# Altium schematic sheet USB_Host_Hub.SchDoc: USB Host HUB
size A3; Project: STM32MP15-DISCO PI; Date: Not used; ApprovedBy: Not used; CheckedBy: Not used; Author: Not used; CompanyName: STMicroelectronics; DrawnBy: Not used; Engineer: Not used; Organization: Not used; Address1: Not used; Address2: Not used; Address3: Not used; Address4: Not used; DocumentNumber: 12; Revision: Not used; SheetNumber: 12; SheetTotal: 17
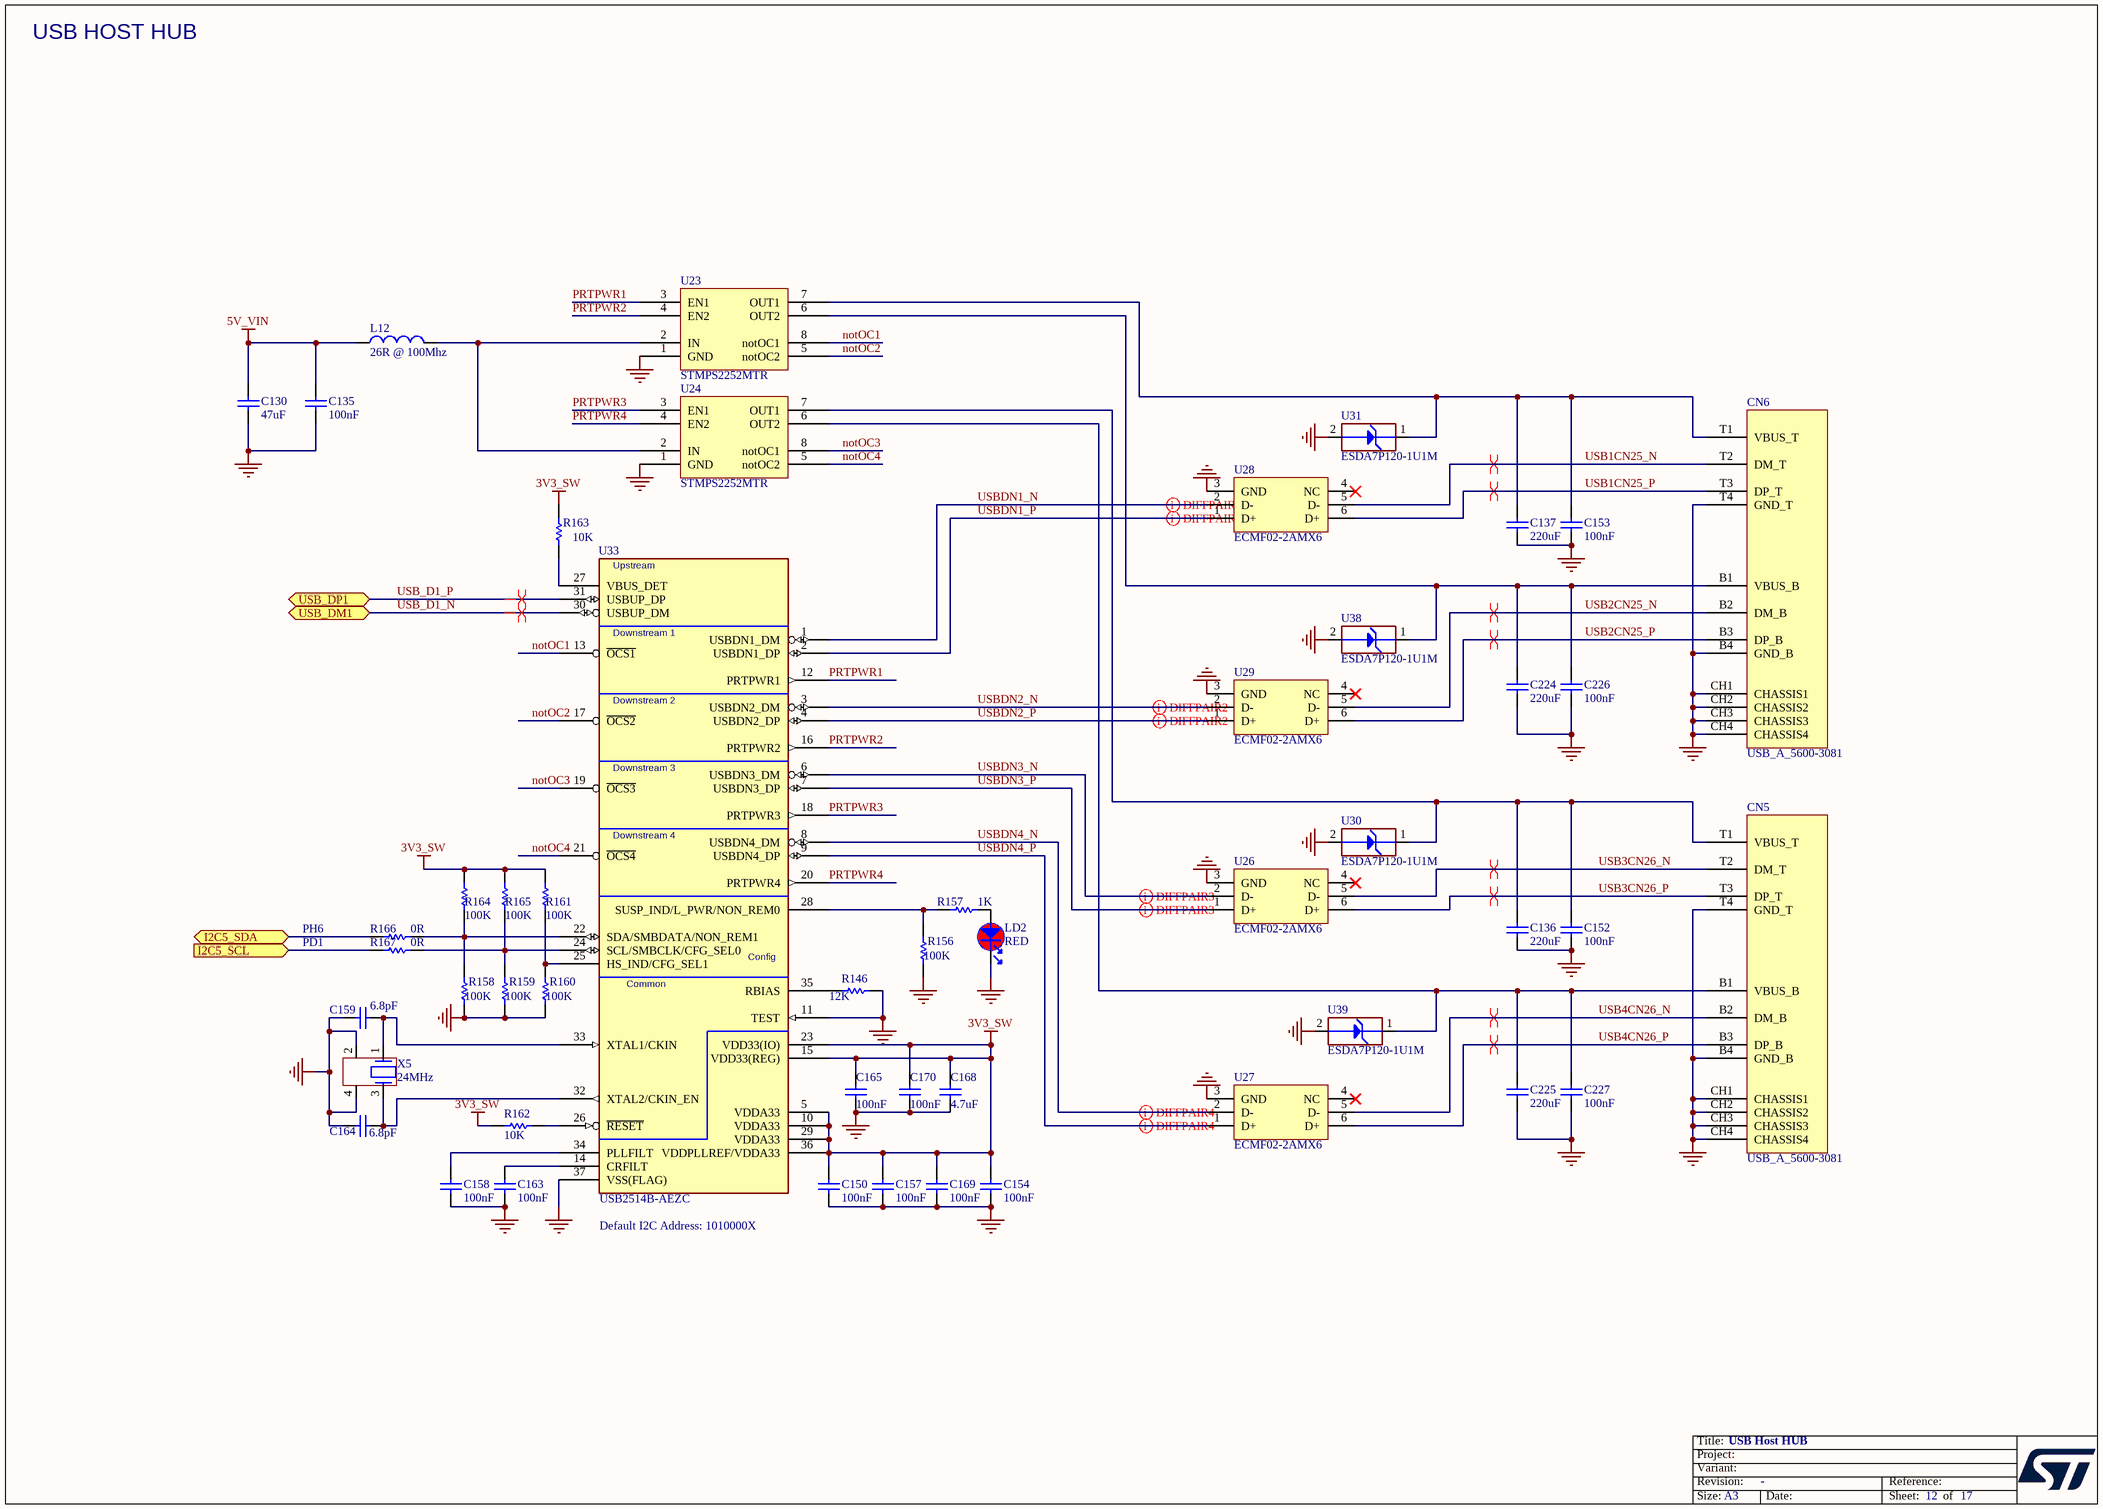
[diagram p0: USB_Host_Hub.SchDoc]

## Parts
C130  value 47uF  [C1206_H1P6]  (hidden comment: Capacitor)
C135  value 100nF  [C0402]  (hidden comment: Capacitor)
C136  value 220uF  [C1206_H1P6]  (hidden comment: Capacitor)
C137  value 220uF  [C1206_H1P6]  (hidden comment: Capacitor)
C150  value 100nF  [C0402]  (hidden comment: Capacitor)
C152  value 100nF  [C0402]  (hidden comment: Capacitor)
C153  value 100nF  [C0402]  (hidden comment: Capacitor)
C154  value 100nF  [C0402]  (hidden comment: Capacitor)
C157  value 100nF  [C0402]  (hidden comment: Capacitor)
C158  value 100nF  [C0402]  (hidden comment: Capacitor)
C159  value 6.8pF  [C0402]  (hidden comment: Capacitor)
C163  value 100nF  [C0402]  (hidden comment: Capacitor)
C164  value 6.8pF  [C0402]  (hidden comment: Capacitor)
C165  value 100nF  [C0402]  (hidden comment: Capacitor)
C168  value 4.7uF  [C0402]  (hidden comment: Capacitor)
C169  value 100nF  [C0402]  (hidden comment: Capacitor)
C170  value 100nF  [C0402]  (hidden comment: Capacitor)
C224  value 220uF  [C1206_H1P6]  (hidden comment: Capacitor)
C225  value 220uF  [C1206_H1P6]  (hidden comment: Capacitor)
C226  value 100nF  [C0402]  (hidden comment: Capacitor)
C227  value 100nF  [C0402]  (hidden comment: Capacitor)
CN5  value USB_A_5600-3081  [CON_DUAL-USB-TYPE-A_CONEXCON_5600-3081]  (hidden comment: USB_DUAL_TYPEA_5600-3081)
CN6  value USB_A_5600-3081  [CON_DUAL-USB-TYPE-A_CONEXCON_5600-3081]  (hidden comment: USB_DUAL_TYPEA_5600-3081)
L12  value 26R @ 100Mhz  [FIL_0603_H0P65]  (hidden comment: BEAD)
LD2  value RED  [LED_0603_RED]  (hidden comment: LED_red)
R146  value 12K  [R0402]  (hidden comment: Resistor)
R156  value 100K  [R0402]  (hidden comment: Resistor)
R157  value 1K  [R0402]  (hidden comment: Resistor)
R158  value 100K  [R0402]  (hidden comment: Resistor)
R159  value 100K  [R0402]  (hidden comment: Resistor)
R160  value 100K  [R0402]  (hidden comment: Resistor)
R161  value 100K  [R0402]  (hidden comment: Resistor)
R162  value 10K  [R0402]  (hidden comment: Resistor)
R163  value 10K  [R0402]  (hidden comment: Resistor)
R164  value 100K  [R0402]  (hidden comment: Resistor)
R165  value 100K  [R0402]  (hidden comment: Resistor)
R166  value 0R  [R0402]  (hidden comment: Resistor)
R167  value 0R  [R0402]  (hidden comment: Resistor)
U23  STMPS2252MTR  [ICC_SO8_5X4_P127]
U24  STMPS2252MTR  [ICC_SO8_5X4_P127]
U26  ECMF02-2AMX6  [ESD_QFN-6L_1P7X1P5_P050]
U27  ECMF02-2AMX6  [ESD_QFN-6L_1P7X1P5_P050]
U28  ECMF02-2AMX6  [ESD_QFN-6L_1P7X1P5_P050]
U29  ECMF02-2AMX6  [ESD_QFN-6L_1P7X1P5_P050]
U30  value ESDA7P120-1U1M  [ESD_QFN1610_2N_1K_2A]  (hidden comment: ESD-TRANSIL)
U31  value ESDA7P120-1U1M  [ESD_QFN1610_2N_1K_2A]  (hidden comment: ESD-TRANSIL)
U33  USB2514B-AEZC  [ICC_QFN36-EPAD_6X6_P050]
U38  value ESDA7P120-1U1M  [ESD_QFN1610_2N_1K_2A]  (hidden comment: ESD-TRANSIL)
U39  value ESDA7P120-1U1M  [ESD_QFN1610_2N_1K_2A]  (hidden comment: ESD-TRANSIL)
X5  value 24MHz  [CRY_NX2016SA_4P]  (hidden comment: XTAL_4_PINS)

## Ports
I2C5_SCL (in), I2C5_SDA (bidir), USB_DM1 (bidir), USB_DP1 (bidir)

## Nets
3V3_SW: C150.2 C154.2 C157.2 C165.2 C168.2 C169.2 C170.2 R161.2 R162.1 R163.2 R164.2 R165.2 U33.5(VDDA33) U33.10(VDDA33) U33.15(VDD33(REG)) U33.23(VDD33(IO)) U33.29(VDDA33) U33.36(VDDPLLREF/VDDA33)
5V_VIN: C130.2 C135.2 L12.1
GND: C130.1 C135.1 C136.1 C137.1 C150.1 C152.1 C153.1 C154.1 C157.1 C158.1 C159.1 C163.1 C164.1 C165.1 C168.1 C169.1 C170.1 C224.1 C225.1 C226.1 C227.1 CN5.B4(GND_B) CN5.CH1(CHASSIS1) CN5.CH2(CHASSIS2) CN5.CH3(CHASSIS3) CN5.CH4(CHASSIS4) CN5.T4(GND_T) CN6.B4(GND_B) CN6.CH1(CHASSIS1) CN6.CH2(CHASSIS2) CN6.CH3(CHASSIS3) CN6.CH4(CHASSIS4) CN6.T4(GND_T) LD2.2 R146.1 R156.1 R158.1 R159.1 R160.1 U23.1(GND) U24.1(GND) U26.3(GND) U27.3(GND) U28.3(GND) U29.3(GND) U30.2(GND) U31.2(GND) U33.11(TEST) U33.37(VSS(FLAG)) U38.2(GND) U39.2(GND) X5.2 X5.4
I2C5_SCL: R167.1 ; port I2C5_SCL
I2C5_SDA: R166.1 ; port I2C5_SDA
notOC1: U23.8(notOC1) U33.13(~{OCS1})
notOC2: U23.5(notOC2) U33.17(~{OCS2})
notOC3: U24.8(notOC1) U33.19(~{OCS3})
notOC4: U24.5(notOC2) U33.21(~{OCS4})
PRTPWR1: U23.3(EN1) U33.12(PRTPWR1)
PRTPWR2: U23.4(EN2) U33.16(PRTPWR2)
PRTPWR3: U24.3(EN1) U33.18(PRTPWR3)
PRTPWR4: U24.4(EN2) U33.20(PRTPWR4)
USB1CN25_N: CN6.T2(DM_T) U28.5(D-)
USB1CN25_P: CN6.T3(DP_T) U28.6(D+)
USB2CN25_N: CN6.B2(DM_B) U29.5(D-)
USB2CN25_P: CN6.B3(DP_B) U29.6(D+)
USB3CN26_N: CN5.T2(DM_T) U26.5(D-)
USB3CN26_P: CN5.T3(DP_T) U26.6(D+)
USB4CN26_N: CN5.B2(DM_B) U27.5(D-)
USB4CN26_P: CN5.B3(DP_B) U27.6(D+)
USB_D1_N: U33.30(USBUP_DM) ; port USB_DM1
USB_D1_P: U33.31(USBUP_DP) ; port USB_DP1
USBDN1_N: U28.2(D-) U33.1(USBDN1_DM)
USBDN1_P: U28.1(D+) U33.2(USBDN1_DP)
USBDN2_N: U29.2(D-) U33.3(USBDN2_DM)
USBDN2_P: U29.1(D+) U33.4(USBDN2_DP)
USBDN3_N: U26.2(D-) U33.6(USBDN3_DM)
USBDN3_P: U26.1(D+) U33.7(USBDN3_DP)
USBDN4_N: U27.2(D-) U33.8(USBDN4_DM)
USBDN4_P: U27.1(D+) U33.9(USBDN4_DP)
NetC136_2: C136.2 C152.2 CN5.T1(VBUS_T) U24.7(OUT1) U30.1(IO1)
NetC137_2: C137.2 C153.2 CN6.T1(VBUS_T) U23.7(OUT1) U31.1(IO1)
NetC158_2: C158.2 U33.34(PLLFILT)
NetC159_2: C159.2 U33.33(XTAL1/CKIN) X5.1
NetC163_2: C163.2 U33.14(CRFILT)
NetC164_2: C164.2 U33.32(XTAL2/CKIN_EN) X5.3
NetC224_2: C224.2 C226.2 CN6.B1(VBUS_B) U23.6(OUT2) U38.1(IO1)
NetC225_2: C225.2 C227.2 CN5.B1(VBUS_B) U24.6(OUT2) U39.1(IO1)
NetL12_2: L12.2 U23.2(IN) U24.2(IN)
NetLD2_1: LD2.1 R157.1
NetR146_2: R146.2 U33.35(RBIAS)
NetR156_2: R156.2 R157.2 U33.28(SUSP_IND/L_PWR/NON_REM0)
NetR158_2: R158.2 R164.1 R166.2 U33.22(SDA/SMBDATA/NON_REM1)
NetR159_2: R159.2 R165.1 R167.2 U33.24(SCL/SMBCLK/CFG_SEL0)
NetR160_2: R160.2 R161.1 U33.25(HS_IND/CFG_SEL1)
NetR162_2: R162.2 U33.26(~{RESET})
NetR163_1: R163.1 U33.27(VBUS_DET)

Not connected (* = marked no-connect by the designer): U26 4(NC)*; U27 4(NC)*; U28 4(NC)*; U29 4(NC)*

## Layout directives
differential pair: USB1CN25_N, USB1CN25_P, USB2CN25_N, USB2CN25_P, USB3CN26_N, USB3CN26_P, USB4CN26_N, USB4CN26_P, USB_D1_N, USB_D1_P, USBDN1_N, USBDN1_P, USBDN2_N, USBDN2_P, USBDN3_N, USBDN3_P, USBDN4_N, USBDN4_P

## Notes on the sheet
- USB HOST HUB
- PH6
- PD1
- Default I2C Address: 1010000X

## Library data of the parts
C130 = MCD-02263: Capacitor, MLCC, 47uF, 25V, X5R, 20%, 1206, T=1.6mm; Part_Preference: Recommended; Manufacturer: MURATA; Manufacturer_Part_Number: GRM31CR61E476ME44; Component_Country_Of_Origin: Japan°°; ShowFields: YES; ID: 4363
C135 C150 C152-C154 C157 C158 C163 C165 C169 C170 C226 C227 = MCD-00006: Capacitor, MLCC, 100nF, 16V, X7R, +/-10%, 0402, T=0.5mm; Manufacturer_Part_Number: CC0402KRX7R7BB104; Manufacturer: YAGEO; Part_Preference: Recommended; Partial_Alternate_Internal_Part_Number: MCD-03299; Order_Code_RS: 9402047; Component_Country_Of_Origin: China; ShowFields: YES; ID: 2474
C136 C137 C224 C225 = MCD-00104: Capacitor, MLCC, 220uF, 6V3, X5R, +/-20%, 1206, T=1.6mm; Manufacturer_Part_Number: GRM31CR60J227ME11; Manufacturer: MURATA; Part_Preference: Recommended; Order_Code_RS: 170-6396; Component_Country_Of_Origin: Japan°°; ShowFields: YES; ID: 2764
C159 C164 = MCD-00674: Capacitor, MLCC, 6.8pF, 50V, NPO, +/-0.25pF, 0402, T=0.5mm; Manufacturer_Part_Number: CC0402CRNPO9BN6R8; Manufacturer: YAGEO; Part_Preference: Recommended; Component_Country_Of_Origin: China; ShowFields: YES; ID: 3068
C168 = MCD-01356: Capacitor, MLCC, 4.7uF, 6V3, X5R, +/-20%, 0402, T=0.5mm; Manufacturer_Part_Number: GRM155R60J475ME47; Manufacturer: MURATA; Part_Preference: Recommended; Partial_Alternate_Internal_Part_Number: MCD-04455; Order_Code_RS: 814-5230; Component_Country_Of_Origin: Japan°°; ShowFields: YES; ID: 3456
CN5 CN6 = MCD-00109: USB_Dual-TypeA, Receptacle, 8pins, 2.5mm, RA, TH, T= 15.5mm; Manufacturer: CONEXCON; Part_Type: Connector; Part_Preference: Recommended; Partial_Alternate_Internal_Part_Number: MCD-04367; Component_Country_Of_Origin: Unknown; ShowFields: YES; ID: 2756
L12 = MCD-00305: Ferrite bead, 26R @ 100Mhz, +/-25%, 6000mA, 0R007, 0603, T=0.75mm; Manufacturer_Part_Number: BLM18KG260TN1; Manufacturer: MURATA; Part_Type: Inductor; Part_Preference: Recommended; Order_Code_RS: 747-4723; Component_Country_Of_Origin: Japan°°; ShowFields: YES; ID: 2564
LD2 = MCD-00049: LED, Red, 0603; Manufacturer_Part_Number: 19-213/R6C-AP1Q2B/3T; Manufacturer: EVERLIGHT; Part_Type: Display; Part_Preference: Forbidden; Full_Alternate_Internal_Part_Number: MCD-02899; Component_Country_Of_Origin: China; ShowFields: YES; ID: 2543
R146 = MCD-00187: Resistor, 12K, 0402, +/-1%, 1/16W; Manufacturer_Part_Number: RC0402FR-0712KL; Manufacturer: YAGEO; BMS_Part_Number: 9131030; Part_Preference: Recommended; Component_Country_Of_Origin: China; ShowFields: YES; ID: 2678
R156 R158-R161 R164 R165 = MCD-00059: Resistor, 100K, 0402, +/-1%, 1/16W; Manufacturer_Part_Number: RC0402FR-07100KL; Manufacturer: YAGEO; Part_Preference: Recommended; Partial_Alternate_Internal_Part_Number: MCD-03301; Order_Code_RS: 2421891; Component_Country_Of_Origin: China; ShowFields: YES; ID: 2533
R157 = MCD-00061: Resistor, 1K, 0402, +/-1%,1/16W; Manufacturer_Part_Number: RC0402FR-071KL; Manufacturer: YAGEO; Part_Preference: Recommended; Order_Code_RS: 9239235; Component_Country_Of_Origin: China; ShowFields: YES; ID: 2532
R162 R163 = MCD-00053: Resistor, 10K, 0402, +/-1%, 1/16W; Manufacturer_Part_Number: RC0402FR-0710KL; Manufacturer: YAGEO; BMS_Part_Number: 9131590; Part_Preference: Recommended; Order_Code_RS: 9239359; Component_Country_Of_Origin: China; ShowFields: YES; ID: 2539
R166 R167 = MCD-00052: Resistor, 0R, 0402, +/-5%, 1/16W; Part_Preference: Recommended; Manufacturer: YAGEO; Manufacturer_Part_Number: RC0402JR-070RL; Order_Code_RS: 9232516RL; Component_Country_Of_Origin: China; ShowFields: YES; ID: 2540
U23 U24 = MCD-00123: IC,Dual-Channel-Power-Switch,500mA,100mR,SO8; Manufacturer: STMICROELECTRONICS; BMS_Part_Number: 9159012; Part_Preference: Recommended; Manufacturer_HQ_COO: EU; Component_Country_Of_Origin: China; ShowFields: YES; ID: 2746
U26-U29 = MCD-00649: Common mode filter with ESD protection for USB 2.0 interface; Part_Type: Diode; Manufacturer: STMICROELECTRONICS; BMS_Part_Number: 9151138; Part_Preference: Recommended; Manufacturer_HQ_COO: EU; Component_Country_Of_Origin: China; ShowFields: YES; ID: 3094; Order_Code_RS: 880-5276
U30 U31 U38 U39 = MCD-01026: High power transient voltage suppressor; Part_Type: Diode; Manufacturer: STMICROELECTRONICS; BMS_Part_Number: 9179046; Part_Preference: Recommended; Manufacturer_HQ_COO: EU; Component_Country_Of_Origin: China; ShowFields: YES; ID: 2997; Order_Code_RS: 190-7605
U33 = MCD-00145: USB HUB 2,0 Controller; Manufacturer: MICROCHIP; Part_Type: IC; Part_Preference: Recommended; Component_Country_Of_Origin: Unknown; ShowFields: YES; ID: 2724; Order_Code_RS: 772-9464
X5 = MCD-01036: Crystal, 24MHz, 6pF, +/-20ppm, 80R, 2x1.6mm; Part_Type: Crystal_Osc; Manufacturer_Part_Number: NX2016SA-24MHZ-EXS00A-CS10820; Manufacturer: NDK; BMS_Part_Number: 9157045; Part_Preference: Recommended; Component_Country_Of_Origin: Japan; ShowFields: YES; ID: 2989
